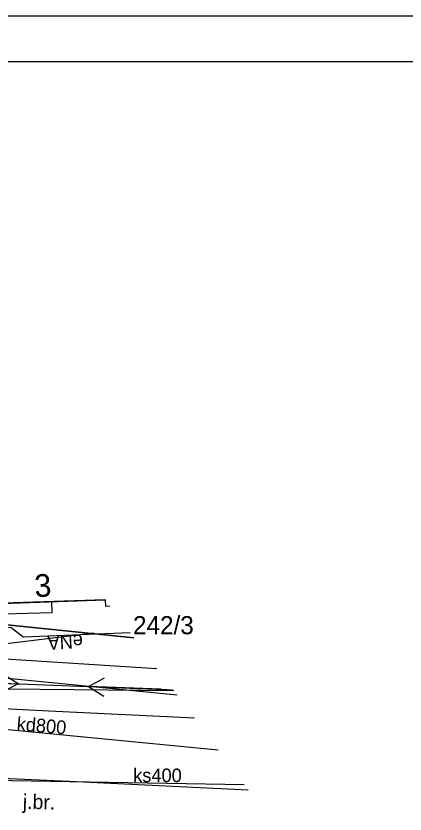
# Model space of a CAD drawing. Extents: x 6512606 to 6513006, y 6022524 to 6022728.
# Drawn here: x 6512819.3 to 6512840.73, y 6022679.94 to 6022723.88 of the extents above; entities that cross this region are included whole.
import ezdxf

# ---------------------------------------------------------------- set-up
doc = ezdxf.new("R2010")
doc.units = 0
for name, color, linetype in [('211-numer działki ewidencyjnej', 7, 'Continuous'), ('217-kontur klasyfikacyjny', 7, 'Continuous'), ('218-kontur użytku gruntowego', 7, 'Continuous'), ('219-działka ewidencyjna', 7, 'Continuous'), ('238-Punkt adresowy budynku', 7, 'Continuous'), ('312-budynek ewidencyjny', 7, 'Continuous'), ('4', 7, 'Continuous'), ('432-Jezdnia', 7, 'Continuous'), ('chodnik (powierzchnia)', 7, 'Continuous'), ('Default', 7, 'Continuous'), ('krawężnik (linia)', 7, 'Continuous'), ('maxp_ramka_2', 7, 'Continuous'), ('przewód elektroenergetyczny (linia)', 7, 'Continuous'), ('przewód elektroenergetyczny (linia)-Atr1', 7, 'Continuous'), ('przewód elektroenergetyczny niskiego napięcia (linia)', 7, 'Continuous'), ('przewód elektroenergetyczny niskiego napięcia (linia) - symbol', 7, 'Continuous'), ('przewód gazowy (linia)', 7, 'Continuous'), ('przewód kanalizacyjny (linia)', 7, 'Continuous'), ('przewód kanalizacyjny (linia)-Atr1', 7, 'Continuous'), ('przewód wodociągowy (linia)', 7, 'Continuous')]:
    doc.layers.add(name, color=color, linetype=linetype)

# ---------------------------------------------------------------- blocks, each defined once
blk = doc.blocks.new('PE04')
at = {"layer": 'Default'}
for p, q in [((46.5, 0), (37.84, 5)), ((6.5, 0), (0, 0)), ((6.5, 0), (16.5, 0)), ((16.5, 0), (26.5, 0)), ((26.5, 0), (36.5, 0)), ((36.5, 0), (46.5, 0)), ((46.5, 0), (37.84, -5)), ((46.5, 0), (50, 0))]:
    blk.add_line(p, q, dxfattribs=at)

msp = doc.modelspace()

# ---------------------------------------------------------------- linework, layer by layer
at = {"layer": '217-kontur klasyfikacyjny'}
for points in [[(6512824.225, 6022691.737), (6512810.17, 6022691.24)], [(6512810.17, 6022691.24), (6512824.225, 6022691.737)], [(6512810.17, 6022691.24), (6512825.794, 6022689.652)]]:
    msp.add_lwpolyline(points, dxfattribs=at)
at = {"layer": '218-kontur użytku gruntowego'}
for points in [[(6512824.225, 6022691.737), (6512810.17, 6022691.24)], [(6512810.17, 6022691.24), (6512824.225, 6022691.737)], [(6512825.794, 6022689.652), (6512810.17, 6022691.24)], [(6512810.17, 6022691.24), (6512825.794, 6022689.652)]]:
    msp.add_lwpolyline(points, dxfattribs=at)
at = {"layer": '219-działka ewidencyjna'}
for points in [[(6512810.17, 6022691.24), (6512824.225, 6022691.737)], [(6512810.17, 6022691.24), (6512825.794, 6022689.652)]]:
    msp.add_lwpolyline(points, dxfattribs=at)
at = {"layer": '312-budynek ewidencyjny'}
msp.add_lwpolyline([(6512824.223, 6022691.739), (6512810.11, 6022691.27)], dxfattribs=at)
at = {"layer": '4'}
for points in [[(6512810.17, 6022691.24), (6512824.225, 6022691.737)], [(6512810.17, 6022691.24), (6512825.794, 6022689.652)]]:
    msp.add_lwpolyline(points, dxfattribs=at)
at = {"layer": 'chodnik (powierzchnia)'}
msp.add_lwpolyline([(6512810.11, 6022691.27), (6512812.85, 6022691.36), (6512812.88, 6022690.46), (6512815.82, 6022690.56), (6512815.79, 6022691.46), (6512818.59, 6022691.55), (6512818.61, 6022690.96), (6512821.3, 6022691.04), (6512821.28, 6022691.64), (6512824.22, 6022691.74), (6512824.24, 6022691.39), (6512824.48, 6022691.398)], dxfattribs=at)
at = {"layer": 'krawężnik (linia)'}
for points in [[(6512829.131, 6022685.216), (6512821.11, 6022685.6), (6512818.61, 6022685.73), (6512810.65, 6022686.18)], [(6512809.1, 6022682.34), (6512822.64, 6022681.73), (6512832.098, 6022681.273)]]:
    msp.add_lwpolyline(points, dxfattribs=at)
at = {"layer": 'maxp_ramka_2'}
for points in [[(6512605.658, 6022723.882), (6513005.658, 6022723.882), (6513005.658, 6022523.882), (6512605.658, 6022523.882)], [(6512618.158, 6022526.382), (6512618.158, 6022721.382), (6513003.158, 6022721.382), (6513003.158, 6022526.382)]]:
    msp.add_lwpolyline(points, close=True, dxfattribs=at)
at = {"layer": 'przewód elektroenergetyczny (linia)'}
for points in [[(6512804.83, 6022691.6), (6512805.89, 6022689.92), (6512810.59, 6022690), (6512816.98, 6022689.19), (6512818.13, 6022690.17), (6512819.01, 6022690.24), (6512819.69, 6022689.7), (6512825.585, 6022689.929)], [(6512827.998, 6022686.723), (6512793.03, 6022687.08), (6512782.71, 6022686.93), (6512780.71, 6022686.29)]]:
    msp.add_lwpolyline(points, dxfattribs=at)
at = {"layer": 'przewód elektroenergetyczny niskiego napięcia (linia)'}
msp.add_lwpolyline([(6512814.78, 6022687.29), (6512827.947, 6022686.79)], dxfattribs=at)
at = {"layer": 'przewód gazowy (linia)'}
msp.add_lwpolyline([(6512808.91, 6022689.46), (6512818.41, 6022688.5), (6512827.069, 6022687.957)], dxfattribs=at)
at = {"layer": 'przewód kanalizacyjny (linia)'}
for points in [[(6512823.6, 6022689.9), (6512818.78, 6022689.32), (6512796.26, 6022688.12)], [(6512808.63, 6022685.58), (6512830.439, 6022683.477)], [(6512810.52, 6022681.93), (6512831.877, 6022681.566)]]:
    msp.add_lwpolyline(points, dxfattribs=at)
at = {"layer": 'przewód wodociągowy (linia)'}
msp.add_lwpolyline([(6512828.176, 6022686.486), (6512808.56, 6022688.42), (6512805.7, 6022688.16), (6512805.45, 6022688.13)], dxfattribs=at)

# ---------------------------------------------------------------- block references
at = {"layer": 'przewód elektroenergetyczny niskiego napięcia (linia) - symbol', "xscale": 0.1, "yscale": 0.09999999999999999}
for p, rotation in [((6512814.78, 6022687.29), -2.175000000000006), ((6512827.947, 6022686.79), 177.825)]:
    msp.add_blockref('PE04', p, dxfattribs=dict(at, rotation=rotation))

# ---------------------------------------------------------------- texts
at = {"layer": '211-numer działki ewidencyjnej'}
msp.add_text('242/3', height=1, dxfattribs=at).set_placement((6512825.75, 6022689.84))
at = {"layer": '238-Punkt adresowy budynku'}
msp.add_text('3', height=1.25, rotation=2.916, dxfattribs=at).set_placement((6512820.35, 6022691.88))
at = {"layer": '4'}
msp.add_text('242/3', height=1, dxfattribs=at).set_placement((6512825.75, 6022689.84))
at = {"layer": '432-Jezdnia'}
msp.add_text('j.br.', height=0.8, rotation=358.224, dxfattribs=at).set_placement((6512819.67, 6022680.24))
at = {"layer": 'przewód elektroenergetyczny (linia)-Atr1'}
msp.add_text('eNA', height=0.75, rotation=183.02, dxfattribs=at).set_placement((6512822.97, 6022689.83))
at = {"layer": 'przewód kanalizacyjny (linia)-Atr1'}
for s, rotation, p in [('kd800', 355.309, (6512819.32, 6022684.55)), ('ks400', 359.926, (6512825.76, 6022681.7))]:
    msp.add_text(s, height=0.75, rotation=rotation, dxfattribs=at).set_placement(p)

doc.saveas('drawing.dxf')
